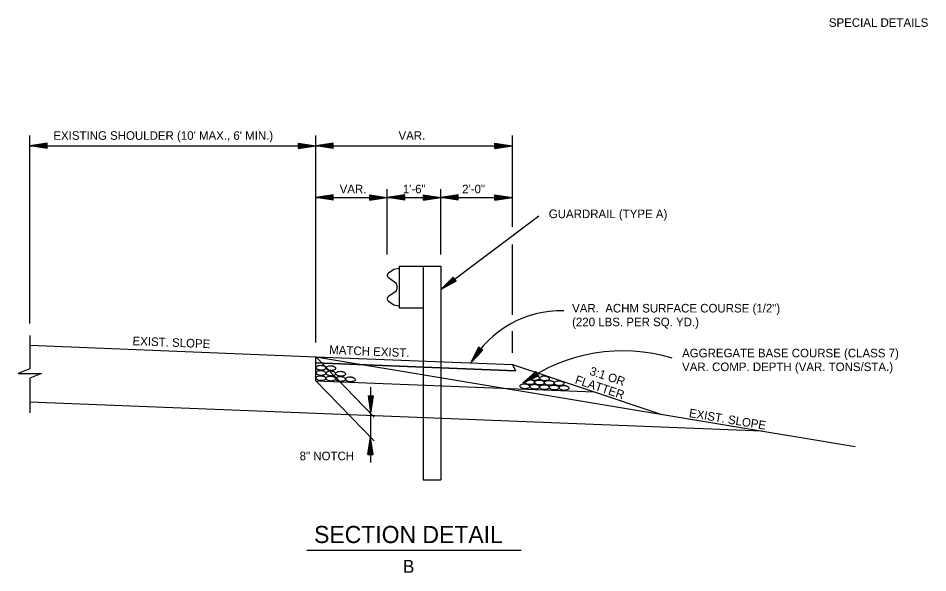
# Model space of a CAD drawing. Extents: x 1374136 to 1374281, y 380549 to 380948.
# Drawn here: x 1374212.7 to 1374276.3, y 380909 to 380947.8 of the extents above; entities that cross this region are included whole.
import ezdxf

# ---------------------------------------------------------------- set-up
doc = ezdxf.new("R2010")
doc.units = 0
for name, color, linetype in [('C-ANNO-TEXT', 7, 'Continuous'), ('Default', 7, 'Continuous'), ('G-ANNO-TEXT', 7, 'Continuous'), ('R_Draft', 7, 'Continuous')]:
    doc.layers.add(name, color=color, linetype=linetype)

msp = doc.modelspace()

# ---------------------------------------------------------------- linework, layer by layer
at = {"layer": 'C-ANNO-TEXT'}
msp.add_lwpolyline([(1374213.507, 380925.562), (1374213.507, 380923.232), (1374212.696, 380922.908), (1374214.318, 380922.908), (1374213.507, 380922.585), (1374213.507, 380920.16)], dxfattribs=at)
at = {"layer": 'Default'}
for p, q in [((1374213.507, 380926.408), (1374213.507, 380939.572)), ((1374233.507, 380925.083), (1374233.507, 380939.572)), ((1374247.257, 380933.189), (1374247.257, 380939.572)), ((1374214.724, 380939.03), (1374213.507, 380938.847)), ((1374214.724, 380938.999), (1374213.711, 380938.847)), ((1374214.724, 380938.967), (1374213.92, 380938.847)), ((1374214.724, 380938.938), (1374214.124, 380938.847)), ((1374214.725, 380938.663), (1374214.724, 380939.03)), ((1374232.29, 380939.03), (1374233.507, 380938.847)), ((1374232.29, 380938.663), (1374232.29, 380939.03)), ((1374232.29, 380938.999), (1374233.303, 380938.847)), ((1374232.29, 380938.967), (1374233.094, 380938.847)), ((1374232.29, 380938.938), (1374232.89, 380938.847)), ((1374234.724, 380939.03), (1374233.507, 380938.847)), ((1374234.724, 380938.999), (1374233.711, 380938.847)), ((1374234.724, 380938.967), (1374233.92, 380938.847)), ((1374234.724, 380938.938), (1374234.124, 380938.847)), ((1374234.725, 380938.663), (1374234.724, 380939.03)), ((1374246.04, 380939.03), (1374247.257, 380938.847)), ((1374246.04, 380938.663), (1374246.04, 380939.03)), ((1374246.04, 380938.999), (1374247.053, 380938.847)), ((1374246.04, 380938.967), (1374246.844, 380938.847)), ((1374246.04, 380938.938), (1374246.64, 380938.847)), ((1374213.507, 380938.847), (1374233.507, 380938.847)), ((1374214.725, 380938.663), (1374213.507, 380938.847)), ((1374214.725, 380938.695), (1374213.711, 380938.847)), ((1374214.725, 380938.726), (1374213.92, 380938.847)), ((1374214.725, 380938.756), (1374214.124, 380938.847)), ((1374214.724, 380938.906), (1374214.328, 380938.848)), ((1374214.725, 380938.787), (1374214.328, 380938.848)), ((1374214.725, 380938.875), (1374214.533, 380938.848)), ((1374214.725, 380938.819), (1374214.533, 380938.848)), ((1374232.29, 380938.906), (1374232.686, 380938.848)), ((1374232.29, 380938.875), (1374232.482, 380938.848)), ((1374232.29, 380938.787), (1374232.686, 380938.848)), ((1374232.29, 380938.819), (1374232.482, 380938.848)), ((1374232.29, 380938.663), (1374233.507, 380938.847)), ((1374232.29, 380938.726), (1374233.094, 380938.847)), ((1374232.29, 380938.695), (1374233.303, 380938.847)), ((1374232.29, 380938.756), (1374232.89, 380938.847)), ((1374233.507, 380938.847), (1374247.257, 380938.847)), ((1374234.725, 380938.663), (1374233.507, 380938.847)), ((1374234.725, 380938.695), (1374233.711, 380938.847)), ((1374234.725, 380938.726), (1374233.92, 380938.847)), ((1374234.725, 380938.756), (1374234.124, 380938.847)), ((1374234.724, 380938.906), (1374234.328, 380938.848)), ((1374234.725, 380938.787), (1374234.328, 380938.848)), ((1374234.725, 380938.875), (1374234.533, 380938.848)), ((1374234.725, 380938.819), (1374234.533, 380938.848)), ((1374246.04, 380938.906), (1374246.436, 380938.848)), ((1374246.04, 380938.875), (1374246.232, 380938.848)), ((1374246.04, 380938.787), (1374246.436, 380938.848)), ((1374246.04, 380938.819), (1374246.232, 380938.848)), ((1374246.04, 380938.663), (1374247.257, 380938.847)), ((1374246.04, 380938.726), (1374246.844, 380938.847)), ((1374246.04, 380938.695), (1374247.053, 380938.847)), ((1374246.04, 380938.756), (1374246.64, 380938.847)), ((1374238.507, 380931.246), (1374238.507, 380935.828)), ((1374242.257, 380931.246), (1374242.257, 380935.828)), ((1374234.724, 380935.419), (1374233.507, 380935.236)), ((1374233.507, 380935.236), (1374238.507, 380935.236)), ((1374234.725, 380935.052), (1374233.507, 380935.236)), ((1374234.724, 380935.388), (1374233.711, 380935.236)), ((1374234.725, 380935.084), (1374233.711, 380935.236)), ((1374234.724, 380935.356), (1374233.92, 380935.236)), ((1374234.725, 380935.115), (1374233.92, 380935.236)), ((1374234.724, 380935.327), (1374234.124, 380935.236)), ((1374234.725, 380935.145), (1374234.124, 380935.236)), ((1374234.724, 380935.295), (1374234.328, 380935.237)), ((1374234.725, 380935.176), (1374234.328, 380935.237)), ((1374234.725, 380935.264), (1374234.533, 380935.237)), ((1374234.725, 380935.208), (1374234.533, 380935.237)), ((1374234.725, 380935.052), (1374234.724, 380935.419)), ((1374237.29, 380935.419), (1374238.507, 380935.236)), ((1374237.29, 380935.052), (1374237.29, 380935.419)), ((1374237.29, 380935.388), (1374238.303, 380935.236)), ((1374237.29, 380935.356), (1374238.094, 380935.236)), ((1374237.29, 380935.327), (1374237.89, 380935.236)), ((1374237.29, 380935.295), (1374237.686, 380935.237)), ((1374237.29, 380935.264), (1374237.482, 380935.237)), ((1374237.29, 380935.176), (1374237.686, 380935.237)), ((1374237.29, 380935.208), (1374237.482, 380935.237)), ((1374237.29, 380935.052), (1374238.507, 380935.236)), ((1374237.29, 380935.115), (1374238.094, 380935.236)), ((1374237.29, 380935.084), (1374238.303, 380935.236)), ((1374237.29, 380935.145), (1374237.89, 380935.236)), ((1374239.724, 380935.419), (1374238.507, 380935.236)), ((1374238.507, 380935.236), (1374242.257, 380935.236)), ((1374239.725, 380935.052), (1374238.507, 380935.236)), ((1374239.724, 380935.388), (1374238.711, 380935.236)), ((1374239.725, 380935.084), (1374238.711, 380935.236)), ((1374239.724, 380935.356), (1374238.92, 380935.236)), ((1374239.725, 380935.115), (1374238.92, 380935.236)), ((1374239.724, 380935.327), (1374239.124, 380935.236)), ((1374239.725, 380935.145), (1374239.124, 380935.236)), ((1374239.724, 380935.295), (1374239.328, 380935.237)), ((1374239.725, 380935.176), (1374239.328, 380935.237)), ((1374239.725, 380935.264), (1374239.533, 380935.237)), ((1374239.725, 380935.208), (1374239.533, 380935.237)), ((1374239.725, 380935.052), (1374239.724, 380935.419)), ((1374241.04, 380935.419), (1374242.257, 380935.236)), ((1374241.04, 380935.052), (1374241.04, 380935.419)), ((1374241.04, 380935.388), (1374242.053, 380935.236)), ((1374241.04, 380935.356), (1374241.844, 380935.236)), ((1374241.04, 380935.327), (1374241.64, 380935.236)), ((1374241.04, 380935.295), (1374241.436, 380935.237)), ((1374241.04, 380935.264), (1374241.232, 380935.237)), ((1374241.04, 380935.176), (1374241.436, 380935.237)), ((1374241.04, 380935.208), (1374241.232, 380935.237)), ((1374241.04, 380935.052), (1374242.257, 380935.236)), ((1374241.04, 380935.115), (1374241.844, 380935.236)), ((1374241.04, 380935.084), (1374242.053, 380935.236)), ((1374241.04, 380935.145), (1374241.64, 380935.236)), ((1374243.474, 380935.419), (1374242.257, 380935.236)), ((1374242.257, 380935.236), (1374247.257, 380935.236)), ((1374243.475, 380935.052), (1374242.257, 380935.236)), ((1374243.474, 380935.388), (1374242.461, 380935.236)), ((1374243.475, 380935.084), (1374242.461, 380935.236)), ((1374243.474, 380935.356), (1374242.67, 380935.236)), ((1374243.475, 380935.115), (1374242.67, 380935.236)), ((1374243.474, 380935.327), (1374242.874, 380935.236)), ((1374243.475, 380935.145), (1374242.874, 380935.236)), ((1374243.474, 380935.295), (1374243.078, 380935.237)), ((1374243.475, 380935.176), (1374243.078, 380935.237)), ((1374243.475, 380935.264), (1374243.283, 380935.237)), ((1374243.475, 380935.208), (1374243.283, 380935.237)), ((1374243.475, 380935.052), (1374243.474, 380935.419)), ((1374246.04, 380935.419), (1374247.257, 380935.236)), ((1374246.04, 380935.052), (1374246.04, 380935.419)), ((1374246.04, 380935.388), (1374247.053, 380935.236)), ((1374246.04, 380935.356), (1374246.844, 380935.236)), ((1374246.04, 380935.327), (1374246.64, 380935.236)), ((1374246.04, 380935.295), (1374246.436, 380935.237)), ((1374246.04, 380935.264), (1374246.232, 380935.237)), ((1374246.04, 380935.176), (1374246.436, 380935.237)), ((1374246.04, 380935.208), (1374246.232, 380935.237)), ((1374246.04, 380935.052), (1374247.257, 380935.236)), ((1374246.04, 380935.115), (1374246.844, 380935.236)), ((1374246.04, 380935.084), (1374247.053, 380935.236)), ((1374246.04, 380935.145), (1374246.64, 380935.236)), ((1374242.257, 380928.783), (1374249.102, 380933.957)), ((1374247.257, 380927.013), (1374247.257, 380931.935)), ((1374238.969, 380930.195), (1374238.593, 380929.943)), ((1374239.332, 380930.266), (1374238.969, 380930.195)), ((1374239.332, 380930.423), (1374242.257, 380930.423)), ((1374239.332, 380930.423), (1374239.332, 380927.498)), ((1374241.007, 380930.423), (1374241.007, 380915.475)), ((1374242.257, 380930.423), (1374242.257, 380915.475)), ((1374238.59, 380929.623), (1374239.102, 380929.264)), ((1374243.119, 380929.661), (1374242.257, 380928.783)), ((1374243.14, 380929.639), (1374242.419, 380928.904)), ((1374243.322, 380929.395), (1374242.419, 380928.904)), ((1374243.16, 380929.61), (1374242.591, 380929.036)), ((1374243.299, 380929.421), (1374242.591, 380929.036)), ((1374243.173, 380929.586), (1374242.751, 380929.156)), ((1374243.281, 380929.446), (1374242.751, 380929.156)), ((1374243.193, 380929.565), (1374242.912, 380929.279)), ((1374243.26, 380929.472), (1374242.912, 380929.279)), ((1374243.211, 380929.539), (1374243.076, 380929.403)), ((1374243.247, 380929.499), (1374243.076, 380929.403)), ((1374243.337, 380929.373), (1374243.119, 380929.661)), ((1374239.184, 380929.105), (1374239.184, 380928.961)), ((1374239.184, 380928.961), (1374239.184, 380928.817)), ((1374243.337, 380929.373), (1374242.257, 380928.783)), ((1374239.102, 380928.658), (1374238.59, 380928.299)), ((1374238.593, 380927.979), (1374238.969, 380927.727)), ((1374238.969, 380927.727), (1374239.332, 380927.656)), ((1374239.332, 380927.498), (1374241.007, 380927.498)), ((1374247.257, 380924.356), (1374247.257, 380925.879)), ((1374213.507, 380924.883), (1374233.507, 380924.083)), ((1374244.896, 380924.755), (1374244.349, 380923.65)), ((1374245.195, 380924.544), (1374244.349, 380923.65)), ((1374244.918, 380924.733), (1374244.465, 380923.818)), ((1374245.172, 380924.563), (1374244.465, 380923.818)), ((1374244.946, 380924.716), (1374244.585, 380923.991)), ((1374245.142, 380924.578), (1374244.585, 380923.991)), ((1374244.969, 380924.7), (1374244.699, 380924.154)), ((1374245.119, 380924.597), (1374244.699, 380924.154)), ((1374244.997, 380924.683), (1374244.818, 380924.325)), ((1374245.093, 380924.613), (1374244.818, 380924.325)), ((1374245.195, 380924.544), (1374244.896, 380924.755)), ((1374245.024, 380924.663), (1374244.937, 380924.49)), ((1374245.068, 380924.633), (1374244.937, 380924.49)), ((1374237.596, 380919.864), (1374233.507, 380924.083)), ((1374233.507, 380924.083), (1374247.257, 380923.533)), ((1374233.507, 380924.083), (1374271.236, 380917.795)), ((1374233.507, 380922.408), (1374233.507, 380924.083)), ((1374233.507, 380923.658), (1374247.474, 380923.1)), ((1374247.257, 380923.533), (1374257.707, 380920.05)), ((1374247.257, 380923.533), (1374247.474, 380923.1)), ((1374248.905, 380923.058), (1374247.982, 380922.243)), ((1374249.105, 380922.749), (1374248.905, 380923.058)), ((1374237.596, 380918.189), (1374233.507, 380922.408)), ((1374233.507, 380922.408), (1374252.967, 380921.63)), ((1374249.105, 380922.749), (1374247.982, 380922.243)), ((1374248.923, 380923.03), (1374248.154, 380922.352)), ((1374249.086, 380922.775), (1374248.154, 380922.352)), ((1374248.939, 380923.004), (1374248.328, 380922.467)), ((1374249.068, 380922.801), (1374248.328, 380922.467)), ((1374248.955, 380922.98), (1374248.498, 380922.578)), ((1374249.052, 380922.824), (1374248.498, 380922.578)), ((1374248.971, 380922.952), (1374248.67, 380922.689)), ((1374249.036, 380922.85), (1374248.67, 380922.689)), ((1374248.989, 380922.926), (1374248.844, 380922.8)), ((1374249.02, 380922.879), (1374248.844, 380922.8)), ((1374237.339, 380921.964), (1374237.339, 380916.688)), ((1374237.163, 380921.347), (1374237.339, 380920.13)), ((1374237.163, 380921.347), (1374237.524, 380921.346)), ((1374237.19, 380921.348), (1374237.339, 380920.331)), ((1374237.224, 380921.346), (1374237.341, 380920.548)), ((1374237.255, 380921.346), (1374237.341, 380920.749)), ((1374237.288, 380921.346), (1374237.343, 380920.951)), ((1374237.318, 380921.351), (1374237.344, 380921.156)), ((1374237.494, 380921.349), (1374237.339, 380920.331)), ((1374237.524, 380921.346), (1374237.339, 380920.13)), ((1374237.459, 380921.348), (1374237.341, 380920.548)), ((1374237.431, 380921.344), (1374237.341, 380920.749)), ((1374237.403, 380921.347), (1374237.343, 380920.951)), ((1374237.372, 380921.346), (1374237.344, 380921.156)), ((1374213.507, 380920.933), (1374264.691, 380918.886)), ((1374237.156, 380917.238), (1374237.339, 380918.455)), ((1374237.183, 380917.237), (1374237.338, 380918.253)), ((1374237.218, 380917.239), (1374237.339, 380918.036)), ((1374237.487, 380917.234), (1374237.338, 380918.253)), ((1374237.518, 380917.237), (1374237.339, 380918.455)), ((1374237.452, 380917.235), (1374237.339, 380918.036)), ((1374237.249, 380917.238), (1374237.338, 380917.835)), ((1374237.282, 380917.239), (1374237.338, 380917.633)), ((1374237.311, 380917.233), (1374237.338, 380917.428)), ((1374237.425, 380917.24), (1374237.338, 380917.835)), ((1374237.397, 380917.236), (1374237.338, 380917.633)), ((1374237.365, 380917.238), (1374237.338, 380917.428)), ((1374237.156, 380917.238), (1374237.518, 380917.237)), ((1374232.89, 380910.538), (1374247.874, 380910.538))]:
    msp.add_line(p, q, dxfattribs=at)
msp.add_lwpolyline([(1374233.507, 380923.658), (1374233.507, 380924.083), (1374247.257, 380923.533), (1374247.474, 380923.1)], close=True, dxfattribs=at)
for centre, radius, start, end in [((1374238.702, 380929.782), 0.195, 124.15804, 234.74711), ((1374238.989, 380929.105), 0.195, 360, 54.74711), ((1374238.989, 380928.817), 0.195, 305.25289, 0), ((1374238.702, 380928.14), 0.195, 125.25289, 235.84196), ((1374250.7, 380919.968), 7.341, 88.82671, 149.8977), ((1374254.984, 380912.471), 12.021, 73.3815, 125.63175)]:
    msp.add_arc(centre, radius, start, end, dxfattribs=at)
for points in [[(1374233.879, 380923.481), (1374233.758, 380923.48), (1374233.612, 380923.431), (1374233.541, 380923.366), (1374233.53, 380923.323), (1374233.565, 380923.249), (1374233.608, 380923.216), (1374233.684, 380923.178), (1374233.804, 380923.144), (1374233.862, 380923.139), (1374233.954, 380923.145), (1374234.052, 380923.162), (1374234.129, 380923.19), (1374234.199, 380923.247), (1374234.211, 380923.29), (1374234.19, 380923.356), (1374234.136, 380923.401), (1374234.086, 380923.438), (1374234.006, 380923.465), (1374233.955, 380923.477), (1374233.879, 380923.481)], [(1374233.879, 380923.116), (1374233.758, 380923.115), (1374233.612, 380923.066), (1374233.541, 380923.001), (1374233.53, 380922.958), (1374233.565, 380922.884), (1374233.608, 380922.851), (1374233.684, 380922.813), (1374233.804, 380922.779), (1374233.862, 380922.774), (1374233.954, 380922.78), (1374234.052, 380922.797), (1374234.129, 380922.825), (1374234.199, 380922.882), (1374234.211, 380922.925), (1374234.19, 380922.991), (1374234.136, 380923.036), (1374234.086, 380923.073), (1374234.006, 380923.1), (1374233.955, 380923.112), (1374233.879, 380923.116)], [(1374234.565, 380923.454), (1374234.444, 380923.452), (1374234.298, 380923.403), (1374234.227, 380923.339), (1374234.216, 380923.295), (1374234.251, 380923.222), (1374234.294, 380923.188), (1374234.37, 380923.151), (1374234.49, 380923.116), (1374234.548, 380923.112), (1374234.64, 380923.117), (1374234.738, 380923.134), (1374234.815, 380923.162), (1374234.885, 380923.219), (1374234.897, 380923.263), (1374234.876, 380923.329), (1374234.822, 380923.373), (1374234.772, 380923.411), (1374234.692, 380923.437), (1374234.641, 380923.449), (1374234.565, 380923.454)], [(1374234.565, 380923.089), (1374234.444, 380923.087), (1374234.298, 380923.038), (1374234.227, 380922.974), (1374234.216, 380922.93), (1374234.251, 380922.857), (1374234.294, 380922.823), (1374234.37, 380922.786), (1374234.49, 380922.751), (1374234.548, 380922.747), (1374234.64, 380922.752), (1374234.738, 380922.769), (1374234.815, 380922.797), (1374234.885, 380922.854), (1374234.897, 380922.898), (1374234.876, 380922.964), (1374234.822, 380923.008), (1374234.772, 380923.046), (1374234.692, 380923.072), (1374234.641, 380923.084), (1374234.565, 380923.089)], [(1374235.251, 380923.062), (1374235.13, 380923.06), (1374234.984, 380923.011), (1374234.913, 380922.946), (1374234.902, 380922.903), (1374234.937, 380922.829), (1374234.98, 380922.796), (1374235.056, 380922.758), (1374235.176, 380922.724), (1374235.234, 380922.719), (1374235.326, 380922.725), (1374235.424, 380922.742), (1374235.501, 380922.77), (1374235.571, 380922.827), (1374235.583, 380922.87), (1374235.562, 380922.936), (1374235.508, 380922.981), (1374235.458, 380923.018), (1374235.378, 380923.045), (1374235.327, 380923.057), (1374235.251, 380923.062)], [(1374233.879, 380922.751), (1374233.758, 380922.75), (1374233.612, 380922.701), (1374233.541, 380922.636), (1374233.53, 380922.593), (1374233.565, 380922.519), (1374233.608, 380922.486), (1374233.684, 380922.448), (1374233.804, 380922.414), (1374233.862, 380922.409), (1374233.954, 380922.415), (1374234.052, 380922.432), (1374234.129, 380922.46), (1374234.199, 380922.517), (1374234.211, 380922.56), (1374234.19, 380922.626), (1374234.136, 380922.671), (1374234.086, 380922.708), (1374234.006, 380922.735), (1374233.955, 380922.747), (1374233.879, 380922.751)], [(1374234.565, 380922.724), (1374234.444, 380922.722), (1374234.298, 380922.673), (1374234.227, 380922.609), (1374234.216, 380922.565), (1374234.251, 380922.492), (1374234.294, 380922.458), (1374234.37, 380922.421), (1374234.49, 380922.386), (1374234.548, 380922.382), (1374234.64, 380922.387), (1374234.738, 380922.404), (1374234.815, 380922.432), (1374234.885, 380922.489), (1374234.897, 380922.533), (1374234.876, 380922.599), (1374234.822, 380922.643), (1374234.772, 380922.681), (1374234.692, 380922.707), (1374234.641, 380922.719), (1374234.565, 380922.724)], [(1374235.251, 380922.697), (1374235.13, 380922.695), (1374234.984, 380922.646), (1374234.913, 380922.581), (1374234.902, 380922.538), (1374234.937, 380922.464), (1374234.98, 380922.431), (1374235.056, 380922.393), (1374235.176, 380922.359), (1374235.234, 380922.354), (1374235.326, 380922.36), (1374235.424, 380922.377), (1374235.501, 380922.405), (1374235.571, 380922.462), (1374235.583, 380922.505), (1374235.562, 380922.571), (1374235.508, 380922.616), (1374235.458, 380922.653), (1374235.378, 380922.68), (1374235.327, 380922.692), (1374235.251, 380922.697)], [(1374235.937, 380922.669), (1374235.816, 380922.667), (1374235.67, 380922.619), (1374235.6, 380922.554), (1374235.588, 380922.51), (1374235.623, 380922.437), (1374235.666, 380922.404), (1374235.742, 380922.366), (1374235.862, 380922.331), (1374235.92, 380922.327), (1374236.012, 380922.333), (1374236.11, 380922.349), (1374236.187, 380922.377), (1374236.258, 380922.434), (1374236.269, 380922.478), (1374236.248, 380922.544), (1374236.194, 380922.589), (1374236.144, 380922.626), (1374236.064, 380922.653), (1374236.013, 380922.664), (1374235.937, 380922.669)], [(1374248.478, 380922.482), (1374248.35, 380922.47), (1374248.207, 380922.436), (1374248.133, 380922.368), (1374248.122, 380922.328), (1374248.157, 380922.251), (1374248.2, 380922.217), (1374248.28, 380922.172), (1374248.396, 380922.141), (1374248.454, 380922.14), (1374248.546, 380922.146), (1374248.648, 380922.152), (1374248.725, 380922.187), (1374248.791, 380922.248), (1374248.803, 380922.295), (1374248.782, 380922.361), (1374248.728, 380922.406), (1374248.678, 380922.428), (1374248.598, 380922.462), (1374248.551, 380922.478), (1374248.478, 380922.482)], [(1374248.822, 380922.766), (1374248.702, 380922.764), (1374248.555, 380922.716), (1374248.485, 380922.651), (1374248.473, 380922.607), (1374248.509, 380922.534), (1374248.552, 380922.5), (1374248.628, 380922.463), (1374248.748, 380922.428), (1374248.806, 380922.424), (1374248.897, 380922.43), (1374248.996, 380922.446), (1374249.073, 380922.474), (1374249.143, 380922.531), (1374249.154, 380922.575), (1374249.134, 380922.641), (1374249.08, 380922.686), (1374249.029, 380922.723), (1374248.949, 380922.75), (1374248.899, 380922.761), (1374248.822, 380922.766)], [(1374249.164, 380922.455), (1374249.036, 380922.442), (1374248.893, 380922.408), (1374248.819, 380922.34), (1374248.808, 380922.3), (1374248.843, 380922.223), (1374248.886, 380922.19), (1374248.966, 380922.145), (1374249.082, 380922.114), (1374249.14, 380922.113), (1374249.232, 380922.119), (1374249.334, 380922.124), (1374249.411, 380922.16), (1374249.477, 380922.221), (1374249.489, 380922.268), (1374249.468, 380922.334), (1374249.414, 380922.378), (1374249.364, 380922.401), (1374249.284, 380922.435), (1374249.237, 380922.45), (1374249.164, 380922.455)], [(1374249.508, 380922.739), (1374249.388, 380922.737), (1374249.241, 380922.688), (1374249.171, 380922.624), (1374249.159, 380922.58), (1374249.195, 380922.507), (1374249.238, 380922.473), (1374249.314, 380922.435), (1374249.434, 380922.401), (1374249.492, 380922.396), (1374249.583, 380922.402), (1374249.682, 380922.419), (1374249.759, 380922.447), (1374249.829, 380922.504), (1374249.841, 380922.548), (1374249.82, 380922.614), (1374249.766, 380922.658), (1374249.715, 380922.695), (1374249.635, 380922.722), (1374249.585, 380922.734), (1374249.508, 380922.739)], [(1374249.85, 380922.428), (1374249.722, 380922.415), (1374249.579, 380922.381), (1374249.506, 380922.313), (1374249.494, 380922.273), (1374249.529, 380922.196), (1374249.572, 380922.162), (1374249.652, 380922.117), (1374249.768, 380922.086), (1374249.826, 380922.085), (1374249.918, 380922.091), (1374250.02, 380922.097), (1374250.097, 380922.132), (1374250.163, 380922.193), (1374250.175, 380922.24), (1374250.154, 380922.306), (1374250.1, 380922.351), (1374250.05, 380922.373), (1374249.97, 380922.408), (1374249.923, 380922.423), (1374249.85, 380922.428)], [(1374250.536, 380922.4), (1374250.408, 380922.388), (1374250.266, 380922.353), (1374250.192, 380922.285), (1374250.18, 380922.245), (1374250.215, 380922.168), (1374250.259, 380922.135), (1374250.338, 380922.09), (1374250.454, 380922.059), (1374250.512, 380922.058), (1374250.604, 380922.064), (1374250.706, 380922.069), (1374250.783, 380922.105), (1374250.85, 380922.166), (1374250.861, 380922.213), (1374250.84, 380922.279), (1374250.786, 380922.323), (1374250.736, 380922.346), (1374250.656, 380922.38), (1374250.609, 380922.395), (1374250.536, 380922.4)], [(1374248.133, 380922.181), (1374248.013, 380922.179), (1374247.866, 380922.131), (1374247.796, 380922.066), (1374247.784, 380922.023), (1374247.82, 380921.949), (1374247.863, 380921.916), (1374247.939, 380921.878), (1374248.059, 380921.843), (1374248.117, 380921.839), (1374248.208, 380921.845), (1374248.307, 380921.861), (1374248.384, 380921.889), (1374248.454, 380921.947), (1374248.466, 380921.99), (1374248.445, 380922.056), (1374248.391, 380922.101), (1374248.34, 380922.138), (1374248.26, 380922.165), (1374248.21, 380922.176), (1374248.133, 380922.181)], [(1374248.819, 380922.154), (1374248.699, 380922.152), (1374248.552, 380922.103), (1374248.482, 380922.039), (1374248.47, 380921.995), (1374248.506, 380921.922), (1374248.549, 380921.888), (1374248.625, 380921.851), (1374248.745, 380921.816), (1374248.803, 380921.811), (1374248.894, 380921.817), (1374248.993, 380921.834), (1374249.07, 380921.862), (1374249.14, 380921.919), (1374249.152, 380921.963), (1374249.131, 380922.029), (1374249.077, 380922.073), (1374249.026, 380922.11), (1374248.946, 380922.137), (1374248.896, 380922.149), (1374248.819, 380922.154)], [(1374249.505, 380922.126), (1374249.385, 380922.125), (1374249.238, 380922.076), (1374249.168, 380922.011), (1374249.156, 380921.968), (1374249.192, 380921.894), (1374249.235, 380921.861), (1374249.311, 380921.823), (1374249.431, 380921.788), (1374249.489, 380921.784), (1374249.58, 380921.79), (1374249.679, 380921.807), (1374249.756, 380921.834), (1374249.826, 380921.892), (1374249.838, 380921.935), (1374249.817, 380922.001), (1374249.763, 380922.046), (1374249.712, 380922.083), (1374249.633, 380922.11), (1374249.582, 380922.122), (1374249.505, 380922.126)], [(1374250.191, 380922.099), (1374250.071, 380922.097), (1374249.924, 380922.048), (1374249.854, 380921.984), (1374249.842, 380921.94), (1374249.878, 380921.867), (1374249.921, 380921.833), (1374249.997, 380921.796), (1374250.117, 380921.761), (1374250.175, 380921.756), (1374250.266, 380921.762), (1374250.365, 380921.779), (1374250.442, 380921.807), (1374250.512, 380921.864), (1374250.524, 380921.908), (1374250.503, 380921.974), (1374250.449, 380922.018), (1374250.398, 380922.056), (1374250.319, 380922.082), (1374250.268, 380922.094), (1374250.191, 380922.099)], [(1374250.877, 380922.071), (1374250.757, 380922.07), (1374250.61, 380922.021), (1374250.54, 380921.956), (1374250.529, 380921.913), (1374250.564, 380921.839), (1374250.607, 380921.806), (1374250.683, 380921.768), (1374250.803, 380921.734), (1374250.861, 380921.729), (1374250.952, 380921.735), (1374251.051, 380921.752), (1374251.128, 380921.78), (1374251.198, 380921.837), (1374251.21, 380921.88), (1374251.189, 380921.946), (1374251.135, 380921.991), (1374251.084, 380922.028), (1374251.005, 380922.055), (1374250.954, 380922.067), (1374250.877, 380922.071)]]:
    msp.add_spline(points, degree=3, dxfattribs=at)
at = {"layer": 'R_Draft'}
msp.add_line((1374241.007, 380915.475), (1374242.257, 380915.475), dxfattribs=at)

# ---------------------------------------------------------------- texts
at = {"layer": 'Default'}
for s, height, p in [("EXISTING SHOULDER (10' MAX., 6' MIN.)", 0.6, (1374215.154, 380939.272)), ('VAR.', 0.6, (1374239.293, 380939.272)), ('VAR.', 0.6, (1374235.178, 380935.528)), ('1\'-6"', 0.6, (1374239.594, 380935.528)), ('2\'-0"', 0.6, (1374243.746, 380935.528)), ('GUARDRAIL (TYPE A)', 0.6, (1374249.802, 380933.789)), ('VAR.  ACHM SURFACE COURSE (1/2")', 0.6, (1374251.433, 380927.183)), ('(220 LBS. PER SQ. YD.)', 0.6, (1374251.433, 380926.218)), ('AGGREGATE BASE COURSE (CLASS 7)', 0.6, (1374259.125, 380924.042)), ('VAR. COMP. DEPTH (VAR. TONS/STA.)', 0.6, (1374259.125, 380923.077)), ('8" NOTCH', 0.6, (1374232.379, 380916.839)), ('SECTION DETAIL', 1.2, (1374233.39, 380911.038)), ('B', 0.9, (1374239.602, 380908.954))]:
    msp.add_text(s, height=height, dxfattribs=at).set_placement(p)
for s, rotation, p in [('EXIST. SLOPE', 357.70939, (1374220.682, 380924.897)), ('MATCH EXIST.', 357.70939, (1374234.436, 380924.279)), ('3:1 OR', 341.56505, (1374252.609, 380922.837)), ('FLATTER', 341.56505, (1374251.585, 380922.229)), ('EXIST. SLOPE', 350.53768, (1374259.574, 380919.865))]:
    msp.add_text(s, height=0.6, rotation=rotation, dxfattribs=at).set_placement(p)
at = {"layer": 'G-ANNO-TEXT'}
msp.add_text('SPECIAL DETAILS', height=0.6, dxfattribs=at).set_placement((1374269.39, 380947.181))

doc.saveas('drawing.dxf')
